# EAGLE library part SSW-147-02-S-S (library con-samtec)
THROUGH-HOLE .025" SQ POST SOCKET Source: Samtec SSW.pdf
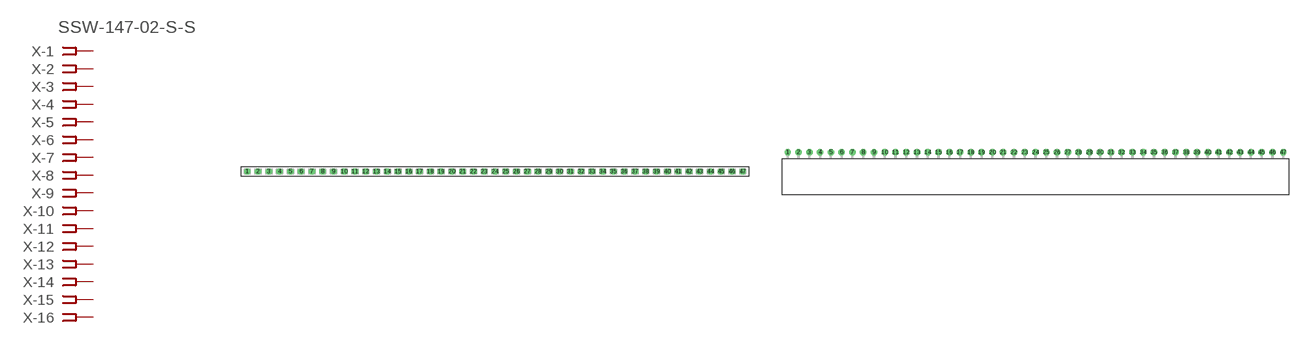
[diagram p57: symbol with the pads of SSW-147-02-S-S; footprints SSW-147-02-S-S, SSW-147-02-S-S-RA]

Designator prefix X; gates -1=FPINV -2=FPIN -3=FPIN -4=FPIN -5=FPIN -6=FPIN -7=FPIN -8=FPIN -9=FPIN -10=FPIN -11=FPIN -12=FPIN -13=FPIN -14=FPIN -15=FPIN -16=FPIN -17=FPIN -18=FPIN -19=FPIN -20=FPIN -21=FPIN -22=FPIN -23=FPIN -24=FPIN -25=FPIN -26=FPIN -27=FPIN -28=FPIN -29=FPIN -30=FPIN -31=FPIN -32=FPIN -33=FPIN -34=FPIN -35=FPIN -36=FPIN -37=FPIN -38=FPIN -39=FPIN -40=FPIN -41=FPIN -42=FPIN -43=FPIN -44=FPIN -45=FPIN -46=FPIN -47=FPIN

## SSW-147-02-S-S (OC_FARNELL: unknown; OC_NEWARK: unknown)  [SSW-147-02-S-S]
1  -1:1  pas
2  -2:1  pas
3  -3:1  pas
4  -4:1  pas
5  -5:1  pas
6  -6:1  pas
7  -7:1  pas
8  -8:1  pas
9  -9:1  pas
10  -10:1  pas
11  -11:1  pas
12  -12:1  pas
13  -13:1  pas
14  -14:1  pas
15  -15:1  pas
16  -16:1  pas
17  -17:1  pas
18  -18:1  pas
19  -19:1  pas
20  -20:1  pas
21  -21:1  pas
22  -22:1  pas
23  -23:1  pas
24  -24:1  pas
25  -25:1  pas
26  -26:1  pas
27  -27:1  pas
28  -28:1  pas
29  -29:1  pas
30  -30:1  pas
31  -31:1  pas
32  -32:1  pas
33  -33:1  pas
34  -34:1  pas
35  -35:1  pas
36  -36:1  pas
37  -37:1  pas
38  -38:1  pas
39  -39:1  pas
40  -40:1  pas
41  -41:1  pas
42  -42:1  pas
43  -43:1  pas
44  -44:1  pas
45  -45:1  pas
46  -46:1  pas
47  -47:1  pas

## SSW-147-02-S-S-RA (OC_FARNELL: unknown; OC_NEWARK: unknown)  [SSW-147-02-S-S-RA]
Pads as for SSW-147-02-S-S

## Footprint SSW-147-02-S-S (pad centres in mm)
THROUGH-HOLE .025" SQ POST SOCKET Source: Samtec SSW.pdf
drill 1 pad 1.5 octagon: 1 -58.42,0; 2 -55.88,0; 3 -53.34,0; 4 -50.8,0; 5 -48.26,0; 6 -45.72,0; 7 -43.18,0; 8 -40.64,0; 9 -38.1,0; 10 -35.56,0; 11 -33.02,0; 12 -30.48,0; 13 -27.94,0; 14 -25.4,0; 15 -22.86,0; 16 -20.32,0; 17 -17.78,0; 18 -15.24,0; 19 -12.7,0; 20 -10.16,0; 21 -7.62,0; 22 -5.08,0; 23 -2.54,0; 24 0,0; 25 2.54,0; 26 5.08,0; 27 7.62,0; 28 10.16,0; 29 12.7,0; 30 15.24,0; 31 17.78,0; 32 20.32,0; 33 22.86,0; 34 25.4,0; 35 27.94,0; 36 30.48,0; 37 33.02,0; 38 35.56,0; 39 38.1,0; 40 40.64,0; 41 43.18,0; 42 45.72,0; 43 48.26,0; 44 50.8,0; 45 53.34,0; 46 55.88,0; 47 58.42,0

## Footprint SSW-147-02-S-S-RA (pad centres in mm)
THROUGH-HOLE .025" SQ POST SOCKET Source: Samtec SSW.pdf
drill 1 pad 1.5 octagon: 1 -58.42,1.524; 2 -55.88,1.524; 3 -53.34,1.524; 4 -50.8,1.524; 5 -48.26,1.524; 6 -45.72,1.524; 7 -43.18,1.524; 8 -40.64,1.524; 9 -38.1,1.524; 10 -35.56,1.524; 11 -33.02,1.524; 12 -30.48,1.524; 13 -27.94,1.524; 14 -25.4,1.524; 15 -22.86,1.524; 16 -20.32,1.524; 17 -17.78,1.524; 18 -15.24,1.524; 19 -12.7,1.524; 20 -10.16,1.524; 21 -7.62,1.524; 22 -5.08,1.524; 23 -2.54,1.524; 24 0,1.524; 25 2.54,1.524; 26 5.08,1.524; 27 7.62,1.524; 28 10.16,1.524; 29 12.7,1.524; 30 15.24,1.524; 31 17.78,1.524; 32 20.32,1.524; 33 22.86,1.524; 34 25.4,1.524; 35 27.94,1.524; 36 30.48,1.524; 37 33.02,1.524; 38 35.56,1.524; 39 38.1,1.524; 40 40.64,1.524; 41 43.18,1.524; 42 45.72,1.524; 43 48.26,1.524; 44 50.8,1.524; 45 53.34,1.524; 46 55.88,1.524; 47 58.42,1.524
